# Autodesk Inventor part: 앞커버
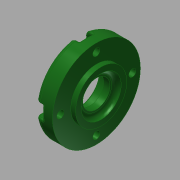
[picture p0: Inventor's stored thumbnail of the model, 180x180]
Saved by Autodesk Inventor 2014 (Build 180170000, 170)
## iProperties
Created: 2015-11
Part Number: 앞커버
Material: 알루미늄 6061
Document SubType Name: Modeling
Designer: mduedu
Density: 2.71 g/cm^3
Appearance: 매끄러움 - 짙은 산림 녹색
Mass: 56.8513 g
Surface Area: 75.7464 cm^2
Volume: 20.9783 cm^3
Author: mduedu
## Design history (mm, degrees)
sketch "스케치1"
  geometry: L1 (-7, 0)-(7, 0); L2 (-7, 0)-(-7, 27.5); L3 (-7, 27.5)-(4, 27.5); L4 (4, 27.5)-(4, 16); L5 (4, 16)-(7, 16); L6 (7, 16)-(7, 0); 2 further points
  constraints: 12 end point, 3 perpendicular, 2 parallel, 1 coincident, 1 horizontal, 1 midpoint
  dimensions: "d0" = 14 distance of L1.start L1.end; "d1" = 55 diameter of L3 L1; "d2" = 3 distance of L4.end L5.end; "d3" = 32 diameter of L5 L1
revolve "회전1" sketch "스케치1" stored, may be unused: angle "d4" = 90 deg
hole "구멍1" diameter "d7" = 25; stored, may be unused: countersink angle "d11" = 90 deg, drill point angle "d13" = 0 deg; dims "d5" = 10, "d6" = 10, "d8" = 6, "d9" = 4, "d10" = 2, "d12" = 3
hole "구멍2" diameter "d16" = 25; stored, may be unused: countersink angle "d20" = 90 deg, drill point angle "d22" = 0 deg; dims "d17" = 6, "d18" = 4, "d19" = 2, "d21" = 7, "d63" = 10, "d64" = 10
hole "구멍3" diameter "d25" = 17; stored, may be unused: countersink angle "d29" = 90 deg, drill point angle "d31" = 0 deg; dims "d23" = 10, "d24" = 10, "d26" = 6, "d27" = 4, "d28" = 2, "d30" = 4.2
chamfer "모따기1" distance "d32" = 0.6; stored, may be unused: second distance "d33" = 2, angle "d34" = 30 deg
fillet "모깎기1" dims "d35" = 0.3
fillet "모깎기2" dims "d36" = 3
fillet "모깎기3" dims "d37" = 3
sketch "스케치2" dims "d39" = 45
  geometry: C1 r 12.846 at (0, 0) reference; C2 r 24.5 at (0, 0) reference; 6 further points
  constraints: 2 vertical alignment, 1 coincident, 7 other
  dimensions: "d42" = 360 deg dimension on point (0, 0) point (0, 22.5) (derived)
sketch "스케치3"
  geometry: 8 further points
  constraints: 4 coincident
hole "구멍4" sketch "스케치3" at (-22.5, 0), (0, -22.5), (22.5, 0), (0, 22.5) diameter "d44" = 4.5; stored, may be unused: countersink angle "d48" = 90 deg, drill point angle "d50" = 0 deg; dims "d45" = 6, "d46" = 8, "d47" = 4.6, "d49" = 8
sketch "스케치4"
  geometry: L1 (-4, 0)-(-4, -4.708); L2 (4, 0)-(4, -4.708); A1 r 4 centre (0, 0) between (-4, 0) and (4, 0) reference; A2 r 27.5 centre (0, 22.5) between (-4, -4.708) and (4, -4.708) reference; 3 further points
  constraints: 4 end point, 4 point on circle, 2 tangent, 1 parallel, 1 vertical
extrude "돌출1" cut sketch "스케치4" stored distance "d51" = 0; taper "d52" = 0 deg
fillet "모깎기5" dims "d56" = 0.3
fillet "모깎기6" dims "d57" = 1
node "솔리드1"
pattern_circular "원형 패턴1" dims angle "d54" = 360 deg
